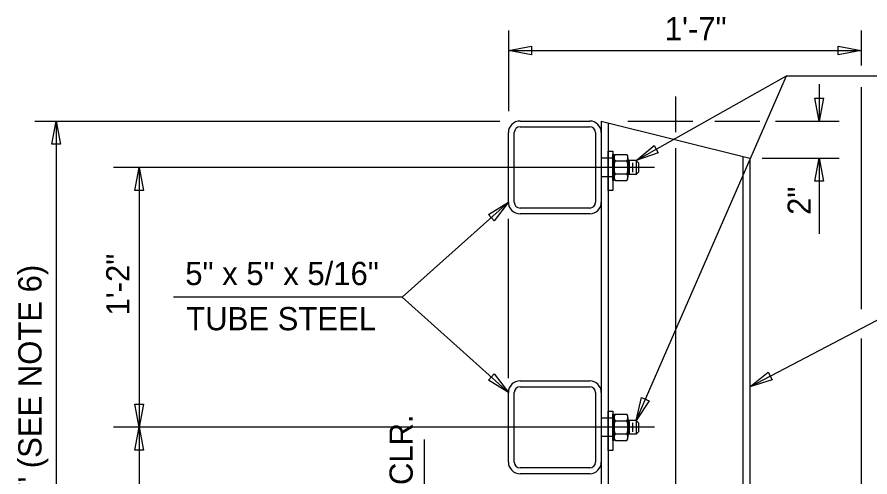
# Model space of a CAD drawing. Extents: x 0 to 45.3, y 0 to 31.4.
# Drawn here: x 31.56 to 39.22, y 10.71 to 14.84 of the extents above; entities that cross this region are included whole.
import ezdxf

# ---------------------------------------------------------------- set-up
doc = ezdxf.new("R2010")
doc.units = 0
for name, color, linetype in [('BRDG_ANNO_General-Notes', 7, 'Continuous'), ('BRDG_BASE_Dtlctrln', 7, 'Continuous'), ('BRDG_BASE_Hidden-Line', 7, 'Continuous'), ('BRDG_BASE_Obj-Line', 7, 'Continuous')]:
    doc.layers.add(name, color=color, linetype=linetype)

msp = doc.modelspace()

# ---------------------------------------------------------------- linework, layer by layer
at = {"layer": 'BRDG_ANNO_General-Notes'}
for p, q in [((35.9724, 14.7163), (35.9724, 13.9926)), ((39.1391, 14.7163), (39.1391, 14.4039)), ((35.9724, 14.5378), (36.179, 14.5766)), ((36.179, 14.5766), (36.179, 14.4991)), ((38.9324, 14.4991), (38.9324, 14.5766)), ((38.9324, 14.5766), (39.1391, 14.5378)), ((35.9724, 14.5378), (39.1391, 14.5378)), ((36.179, 14.4991), (35.9724, 14.5378)), ((39.1391, 14.5378), (38.9324, 14.4991)), ((37.1182, 13.5496), (38.4689, 14.3102)), ((37.1182, 11.2163), (38.4689, 14.3102)), ((38.4689, 14.3102), (43.9932, 14.3102)), ((38.762, 14.2354), (38.762, 13.9037)), ((39.1391, 14.2087), (39.1391, 12.2138)), ((38.7232, 14.1104), (38.8007, 14.1104)), ((38.762, 13.9037), (38.7232, 14.1104)), ((38.8007, 14.1104), (38.762, 13.9037)), ((31.7228, 13.9038), (35.8955, 13.9038)), ((31.876, 13.6971), (31.9147, 13.9038)), ((31.9147, 13.9038), (31.9147, 8.4871)), ((31.9147, 13.9038), (31.9535, 13.6971)), ((37.0435, 13.9037), (37.627, 13.9037)), ((37.8249, 13.9037), (38.2289, 13.9037)), ((38.3691, 13.9037), (38.9402, 13.9037)), ((31.9535, 13.6971), (31.876, 13.6971)), ((37.1182, 13.5496), (37.2793, 13.6848)), ((37.2793, 13.6848), (37.3173, 13.6172)), ((37.3173, 13.6172), (37.1182, 13.5496)), ((38.2501, 13.5704), (38.9402, 13.5704)), ((38.7232, 13.3637), (38.762, 13.5704)), ((38.762, 13.5704), (38.762, 12.8897)), ((38.762, 13.5704), (38.8007, 13.3637)), ((32.6193, 13.2805), (32.6581, 13.4871)), ((32.6581, 13.4871), (32.6581, 11.1538)), ((32.6581, 13.4871), (32.6968, 13.2805)), ((38.8007, 13.3637), (38.7232, 13.3637)), ((32.6968, 13.2805), (32.6193, 13.2805)), ((35.9724, 13.1746), (35.0203, 12.3218)), ((35.7926, 13.0656), (35.9724, 13.1746)), ((35.9724, 13.1746), (35.8443, 13.0078)), ((35.8443, 13.0078), (35.7926, 13.0656)), ((35.9724, 11.5936), (35.9724, 13.0261)), ((38.139, 11.5182), (39.6866, 12.3289)), ((35.0203, 12.3218), (32.9658, 12.3218)), ((35.0203, 12.3218), (35.9724, 11.4663)), ((39.139, 11.9524), (39.139, 9.7586)), ((35.7927, 11.5756), (35.8445, 11.6332)), ((35.8445, 11.6332), (35.9724, 11.4663)), ((38.139, 11.5182), (38.3041, 11.6484)), ((38.3041, 11.6484), (38.3401, 11.5797)), ((35.9724, 11.4663), (35.7927, 11.5756)), ((38.3401, 11.5797), (38.139, 11.5182)), ((37.1182, 11.2163), (37.1654, 11.4211)), ((37.1654, 11.4211), (37.2364, 11.3901)), ((32.6193, 11.3605), (32.6968, 11.3605)), ((32.6581, 11.1538), (32.6193, 11.3605)), ((32.6968, 11.3605), (32.6581, 11.1538)), ((37.2364, 11.3901), (37.1182, 11.2163)), ((32.6193, 10.9471), (32.6581, 11.1538)), ((32.6581, 11.1538), (32.6581, 8.4871)), ((32.6581, 11.1538), (32.6968, 10.9471)), ((35.2178, 11.0432), (35.2178, 9.6537)), ((32.6968, 10.9471), (32.6193, 10.9471))]:
    msp.add_line(p, q, dxfattribs=at)
at = {"layer": 'BRDG_BASE_Dtlctrln'}
for p, q in [((37.4724, 14.1248), (37.4724, 13.8034)), ((37.4724, 13.6611), (37.4724, 9.7726)), ((37.2836, 13.4871), (32.4287, 13.4871)), ((37.2836, 11.1538), (32.4287, 11.1538))]:
    msp.add_line(p, q, dxfattribs=at)
at = {"layer": 'BRDG_BASE_Hidden-Line'}
for p, q in [((36.9099, 13.5704), (36.8057, 13.5704)), ((36.9099, 13.4037), (36.8057, 13.4037)), ((36.9099, 11.2371), (36.8057, 11.2371)), ((36.9203, 11.0704), (36.8057, 11.0704))]:
    msp.add_line(p, q, dxfattribs=at)
at = {"layer": 'BRDG_BASE_Obj-Line'}
for p, q in [((36.0765, 13.9037), (36.7015, 13.9037)), ((36.8057, 13.9037), (36.8057, 10.2371)), ((36.8057, 13.9037), (38.139, 13.5704)), ((36.8682, 13.8881), (36.8682, 10.0704)), ((35.9724, 13.1746), (35.9724, 13.7996)), ((36.0244, 13.1746), (36.0244, 13.7996)), ((36.0765, 13.8517), (36.7015, 13.8517)), ((36.7536, 13.7996), (36.7536, 13.1746)), ((36.8057, 13.7996), (36.8057, 13.1746)), ((36.9203, 13.5743), (36.9203, 13.4871)), ((36.9296, 13.6043), (37.036, 13.6043)), ((37.0453, 13.5743), (37.0453, 13.4871)), ((37.1182, 13.5496), (37.0453, 13.5496)), ((37.0557, 13.5496), (37.0557, 13.4246)), ((37.1182, 13.5496), (37.1182, 13.4246)), ((37.1182, 13.5496), (37.139, 13.5287)), ((38.0765, 13.586), (38.0765, 10.0704)), ((38.139, 13.5704), (38.139, 10.2405)), ((36.9203, 13.4871), (36.9203, 13.3999)), ((36.9296, 13.5457), (37.036, 13.5457)), ((37.0453, 13.4871), (37.0453, 13.3999)), ((37.0869, 13.5287), (37.0869, 13.4454)), ((37.139, 13.5287), (37.139, 13.4454)), ((36.9296, 13.4285), (37.036, 13.4285)), ((37.1182, 13.4246), (37.0453, 13.4246)), ((37.1182, 13.4246), (37.139, 13.4454)), ((36.9296, 13.3699), (37.036, 13.3699)), ((36.7015, 13.1225), (36.0765, 13.1225)), ((36.7015, 13.0704), (36.0765, 13.0704)), ((36.0765, 11.5704), (36.7015, 11.5704)), ((36.0765, 11.5183), (36.7015, 11.5183)), ((35.9724, 10.8412), (35.9724, 11.4663)), ((36.0244, 10.8412), (36.0244, 11.4663)), ((36.7536, 11.4663), (36.7536, 10.8412)), ((36.8057, 11.4663), (36.8057, 10.8412)), ((36.9296, 11.2709), (37.036, 11.2709)), ((36.9203, 11.2409), (36.9203, 11.1538)), ((36.9296, 11.2123), (37.036, 11.2123)), ((37.0453, 11.2409), (37.0453, 11.1538)), ((37.1182, 11.2163), (37.0453, 11.2163)), ((37.0557, 11.2163), (37.0557, 11.0913)), ((37.0869, 11.1954), (37.0869, 11.1121)), ((37.1182, 11.2163), (37.1182, 11.0913)), ((37.1182, 11.2163), (37.139, 11.1954)), ((37.139, 11.1954), (37.139, 11.1121)), ((36.9203, 11.1538), (36.9203, 11.0666)), ((37.0453, 11.1538), (37.0453, 11.0666)), ((37.1182, 11.0913), (37.139, 11.1121)), ((36.9296, 11.0952), (37.036, 11.0952)), ((36.9296, 11.0366), (37.036, 11.0366)), ((37.1182, 11.0913), (37.0453, 11.0913)), ((36.7015, 10.7892), (36.0765, 10.7892)), ((36.7015, 10.7371), (36.0765, 10.7371))]:
    msp.add_line(p, q, dxfattribs=at)
for points in [[(36.8682, 13.6329), (36.9099, 13.6329), (36.9099, 13.2787), (36.8682, 13.2787)], [(36.9099, 13.6043), (36.9203, 13.6043), (36.9203, 13.3699), (36.9099, 13.3699)], [(36.8682, 11.2996), (36.9099, 11.2996), (36.9099, 10.9454), (36.8682, 10.9454)], [(36.9099, 11.2709), (36.9203, 11.2709), (36.9203, 11.0366), (36.9099, 11.0366)]]:
    msp.add_lwpolyline(points, close=True, dxfattribs=at)
for centre, radius, start, end in [((36.0765, 13.7996), 0.1042, 90, 180), ((36.7015, 13.7996), 0.1042, 0, 90), ((36.0765, 13.7996), 0.0521, 90, 180), ((36.7015, 13.7996), 0.0521, 0, 90), ((36.9711, 13.575), 0.0508, 144.7697, 215.2303), ((36.9945, 13.575), 0.0508, 324.7697, 35.2303), ((37.1096, 13.4871), 0.1893, 161.96845, 198.03155), ((36.856, 13.4871), 0.1893, 341.96845, 18.03155), ((36.9711, 13.3992), 0.0508, 144.7697, 215.2303), ((36.9945, 13.3992), 0.0508, 324.7697, 35.2303), ((36.0765, 13.1746), 0.1042, 180, 270), ((36.0765, 13.1746), 0.0521, 180, 270), ((36.7015, 13.1746), 0.0521, 270, 0), ((36.7015, 13.1746), 0.1042, 270, 0), ((36.0765, 11.4663), 0.1042, 90, 180), ((36.7015, 11.4663), 0.1042, 0, 90), ((36.0765, 11.4663), 0.0521, 90, 180), ((36.7015, 11.4663), 0.0521, 0, 90), ((36.9711, 11.2416), 0.0508, 144.7697, 215.2303), ((36.9945, 11.2416), 0.0508, 324.7697, 35.2303), ((37.1096, 11.1538), 0.1893, 161.96845, 198.03155), ((36.856, 11.1538), 0.1893, 341.96845, 18.03155), ((36.9711, 11.0659), 0.0508, 144.7697, 215.2303), ((36.9945, 11.0659), 0.0508, 324.7697, 35.2303), ((36.0765, 10.8412), 0.1042, 180, 270), ((36.0765, 10.8412), 0.0521, 180, 270), ((36.7015, 10.8412), 0.0521, 270, 0), ((36.7015, 10.8412), 0.1042, 270, 0)]:
    msp.add_arc(centre, radius, start, end, dxfattribs=at)

# ---------------------------------------------------------------- texts
at = {"layer": 'BRDG_ANNO_General-Notes'}
for s, height, p in [('1\'-7"', 0.20833, (37.3753, 14.6291)), ('5" x 5" x 5/16"', 0.208333, (33.0726, 12.4307)), ('TUBE STEEL', 0.20833, (33.0812, 12.0251))]:
    msp.add_text(s, height=height, dxfattribs=at).set_placement(p)
for s, height, p in [('2"', 0.20833, (38.686, 13.061)), ('1\'-2"', 0.20833, (32.5714, 12.1577)), ('2\'-8 1/2" (SEE NOTE 6)', 0.208333, (31.7826, 9.6896)), ('1 1/2" CLR.', 0.208333, (35.1136, 9.8391))]:
    msp.add_text(s, height=height, rotation=90, dxfattribs=at).set_placement(p)

doc.saveas('drawing.dxf')
